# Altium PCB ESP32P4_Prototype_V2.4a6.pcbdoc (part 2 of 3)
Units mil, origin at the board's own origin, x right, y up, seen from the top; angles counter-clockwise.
Board outline 8474.8 x 7265.9 mil, 6 copper layers (Top Layer, GND, VCC, VCC1, GND1, Bottom Layer), stack 62.3 mil thick; 189 components, 155 nets, 775 pads, 406 vias.
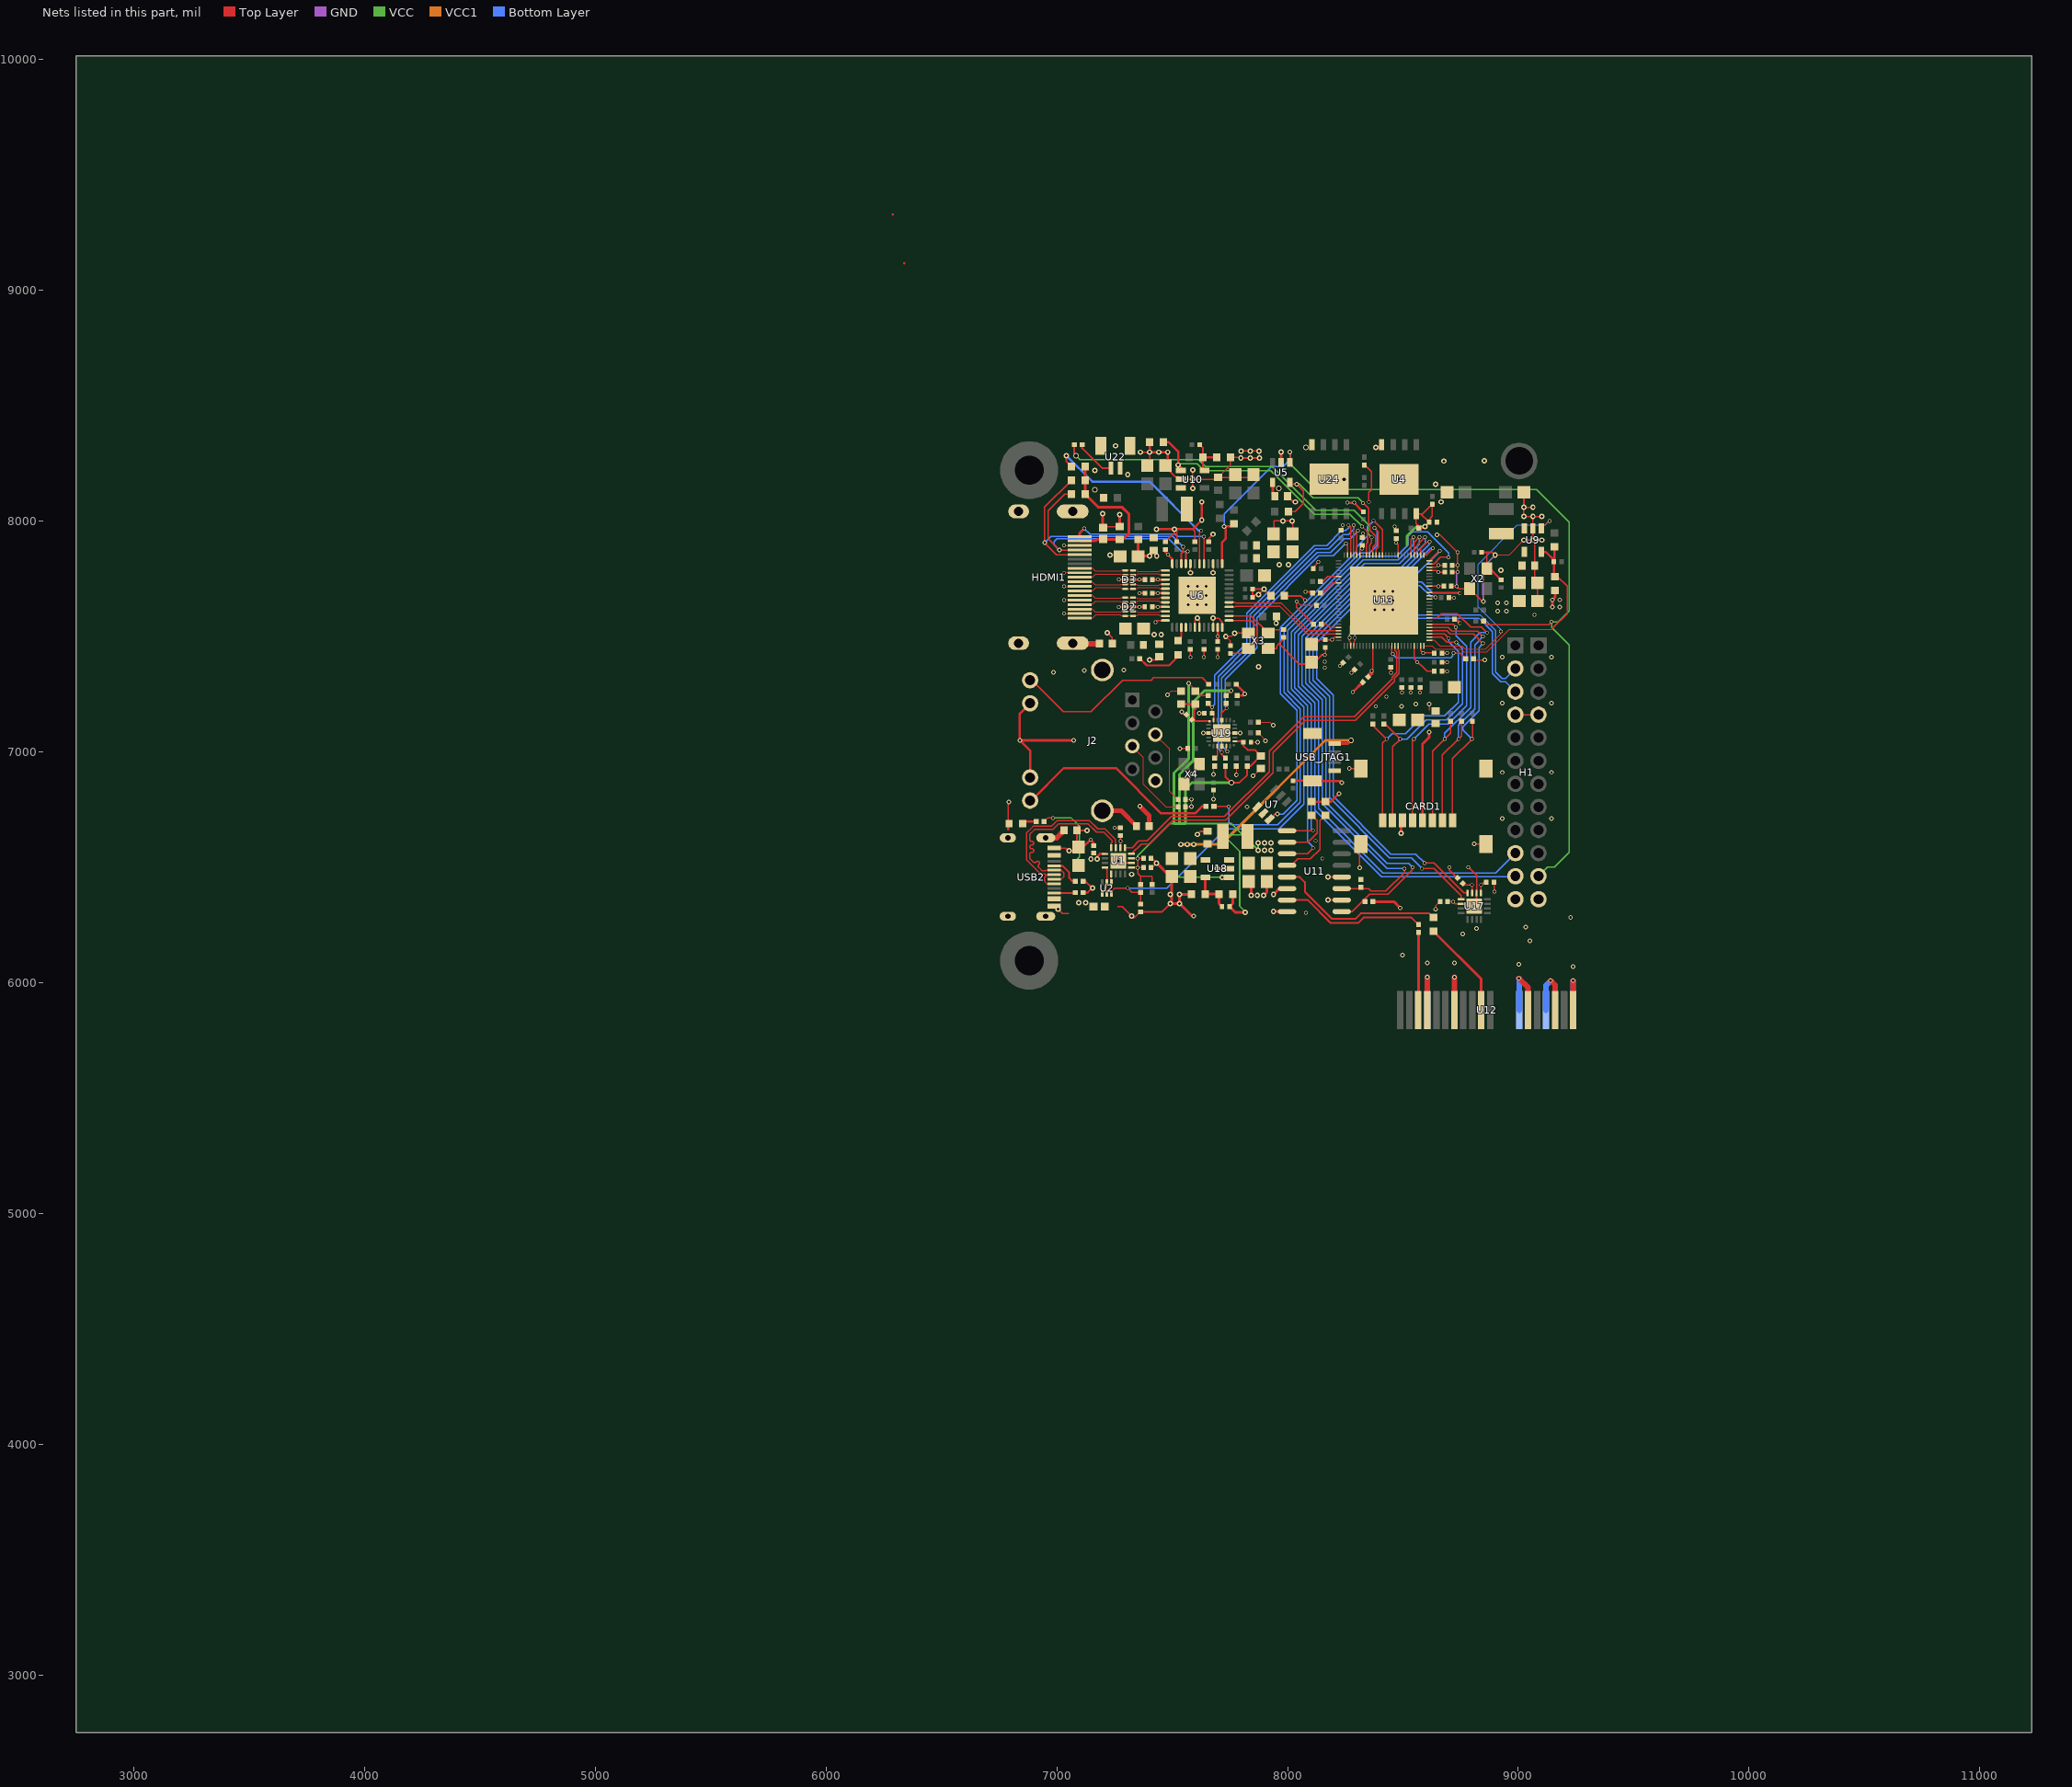
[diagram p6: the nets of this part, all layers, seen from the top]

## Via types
v1: diameter 15.7, hole 11.8, Top Layer to Bottom Layer, 168 vias
v2: diameter 23.6, hole 11.8, Top Layer to Bottom Layer, 139 vias
v3: diameter 19.7, hole 11.8, Top Layer to Bottom Layer, 91 vias
v4: diameter 23.6, hole 15.7, Top Layer to Bottom Layer, 8 vias

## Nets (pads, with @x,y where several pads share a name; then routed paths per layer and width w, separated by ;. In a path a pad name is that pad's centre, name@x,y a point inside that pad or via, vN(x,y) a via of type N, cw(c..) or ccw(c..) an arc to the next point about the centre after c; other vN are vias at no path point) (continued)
3V3_SYS: C2.1 C8.2 C9.2 C19.2 C27.2 C28.2 C29.2 C39.2 C40.2 C42.2 C43.2 C44.2 C45.2 C46.2 C47.2 C48.2 C49.2 C50.2 C51.2 C52.2 C53.2 C84.2 C85.2 C86.2 C90.2 C91.2 C92.2 C99.2 C101.2 C109.2 CARD1.4 L4.2 R1.1 R3.1 R6.2 R11.2 R15.1 R18.1 R19.2 R26.2 R41.2 R42.2 R43.2 U1.1 U1.3 U1.6 U3.2 U4.8 U5.4 U7.1 U9.4 U11.10 U11.12 U13.9 U13.21 U13.51 U13.62 U13.75 U13.77 U13.96 U13.101 U13.102 U17.1 U17.3 U17.6 U19.19 | length 6224.7
  Top Layer w4.7: v3@7573.5,7298.7 7573.5,7295.1 U3.2@7599.5,7269.2
  Top Layer w5: v1(7350.5,6538.2) v1(7350.5,6498.8) 7350.5,6472.2 7362.6,6460.1 7412.6,6460.1 ; v1(8587.6,7428.7) 8635.5,7428.7 C48.2@8636.1,7428.1
  Top Layer w5.9: U3.2@7600.8,7267.5 7624.1,7244.2 R41.2@7655.7,7244.2 ; R42.2@7734.4,7244.2 v3@7753.3,7263.1 ; C109.2@8116.3,7467.3 8134.8,7485.8 C53.2@8163.5,7485.8 8191.9,7485.8 v1(8193.1,7487) 8203.8,7497.7 U13.51@8220.9,7497.7 ; R18.1@8334.8,8243.6 8362.8,8215.6 8362.8,8135 8352.5,8124.7 v1(8352.5,8083.3) ; C52.2@8354.6,7325.7 8369.5,7340.6 U13.62@8369.5,7459.4 ; C46.2@8470.6,7925.2 v1(8470.6,7906.3) 8479.8,7897.1 U13.9@8479.8,7853.1 ; U13.75@8548.7,7459.4 8548.7,7404.5 8603.8,7349.4 C51.2@8636.1,7349.4 ; U13.77@8576.2,7459.4 8576.2,7440.1 v1(8587.6,7428.7) ; C84.2@8759.9,6430 8766.7,6423.2 v1(8799.3,6423.2) ; 8819.2,7398.4 v3(8854.5,7398.4) ; v1(8838.7,6423.2) 8851.3,6435.8 C86.2@8861.6,6435.8 ; 8576.9,8032.2 C2.1@8613.9,7995.3 ; 8576.9,8032.2 U4.8@8557.4,8032.2 8557.4,7990.6 8568.3,7979.7 R19.2@8568.3,7970.2 8588.9,7970.2 C2.1@8613.9,7995.3 ; 8576.9,8032.2 8585.7,8032.2 R15.1@8627.4,8073.9 8627.4,8021.7 8613.9,8008.2 C2.1@8613.9,7995.3
  Top Layer w6.1: U1.6@7275.7,6585.4 v1(7275.7,6612.9) ; v1@7275.7,6613 C39.2@7275.7,6637.8 ; U1.1@7323,6498.8 v1(7350.5,6498.8) C42.2@7375.3,6498.8 ; U1.3@7323,6538.2 v1(7350.5,6538.2) C40.2@7375.3,6538.2 ; R1.1@7362.6,6435.2 7362.6,6460 ; R3.1@7412.6,6435.2 7412.6,6460 ; U13.21@8314.4,7853.1 8314.4,7881.1 C45.2@8323,7889.7 ; C52.2@8349.3,7325.4 8349.3,7336.1 v1(8364.3,7351.1) ; U13.96@8614.6,7718.2 v1(8654,7718.2) C50.2@8676.8,7718.2 ; U13.101@8614.6,7787.1 8645.2,7787.1 v1(8653.1,7779.2) C49.2@8679.9,7779.2 ; U13.102@8614.6,7800.9 8645.2,7800.9 v1(8653.1,7808.8) C47.2@8679.9,7808.8 ; C85.2@8693.9,6351.1 v1(8717.5,6351.1) 8727.3,6341.3 U17.6@8752.1,6341.3 ; U17.3@8799.3,6388.5 v1(8799.3,6423.2) ; U17.1@8838.7,6388.5 v1(8838.7,6423.2)
  Top Layer w7.9: R11.2@7730.5,6938.4 7730.5,6892.5 v4(7756.1,6866.9) 7791.5,6866.9 7825,6900.4 R43.2@7825,6938.4 7839.3,6938.4 C99.2@7883.9,6983 7858.3,7008.6 7826.9,7008.6 7808.4,7027.1 C101.2@7808.4,7042.1 7804.5,7046 U19.19@7771.3,7046 ; v2(8175.8,6358) U11.10@8234.8,6358 ; v2(8175.8,6458) U11.12@8234.8,6458
  Top Layer w8: C52.2@8352.3,7330.8 8363.6,7342.1 8366,7342.1 ; C52.2@8354.3,7325.4 C52.2@8354.6,7325.7
  Top Layer w11.8: R6.2@7762.8,6383.7 7762.8,6343.3 C90.2@7749,6329.5 7773.7,6304.8 v2(7817.3,6304.8) ; U5.4@7935.2,8168.1 7935.2,8118.9 C19.2@7945,8109 ; CARD1.4@8584.8,6703.5 8584.8,7034.2 8614.3,7063.7 v3(8614.3,7085.4)
  VCC w6.1: 7812.9,6641.1 7805,6641.1 7745,6641.1 7736.9,6633 7736.9,6624.4 7792.6,6568.7 7792.6,6331.3 v2@7819.4,6304.4
  VCC w7.9: v1(7350.5,6538.2) 7350.5,6549.9 7490.3,6689.7 7508,6689.7 ; 7556.5,6689.7 7756.4,6689.7 7805,6641.1 v2(7872.5,6573.7) v2(7872.5,6605)
  VCC w11.8: v3(7571,7298) 7571,6971.2 7508,6908.2 7508,6689.7 7531.6,6689.7 ; v3(7755.7,7265) 7640.3,7265 7590.7,7215.3 7590.7,6961.4 7531.6,6902.3 7531.6,6689.7 ; v4(7756.1,6866.9) 7584.8,6866.9 7556.5,6838.6 7556.5,6689.7 7531.6,6689.7 ; 8517.9,7894.4 8517.9,7935.8 8559.2,7977.2 v2(8595.8,7977.2)
  other v1: 8562.6,7388.7 8323,7881.3
  other v2: 7900,6573.7 7927.6,6573.7 7900,6605 7927.6,6605 7964.7,7811.8 8004.1,7811.8
  other v3: 8911.1,7609.9 8949,7609.9 8911.1,7646.4 8949,7646.4
  other v4: 7962.7,8142.5
3V3AUX: R51.2 U12.B10 | length 428.3
  Top Layer w11.8: R51.2@8632,6223.1 8839.6,6015.5 U12.B10@8839.6,5880.8
5V_SYS: C4.1 C41.2 C87.2 C88.2 C89.2 D1.2 R5.1 U1.9 U18.1 U18.4 USB2.A4B9 USB2.B4A9 USB_JTAG1.1 | length 1594.7
  Top Layer w6.1: R5.1@6944.6,6698.7 6959.6,6713.7 v1(6982.6,6713.7)
  Top Layer w10: v2(7175.4,6536.2) 7175.4,6546 7187.1,6557.8 U1.9@7208.8,6557.8
  Top Layer w11.8: USB_JTAG1.1@8203.9,7036 8261.8,7036 v4(8275.7,7050)
  VCC w5.9: 7517.6,6468.7 7529.7,6456.6 v2(7717.2,6456.6)
  VCC w6.1: v1(6982.6,6713.7) 7062.6,6713.7 7097.6,6678.7 7097.6,6545 7075.1,6522.6
  VCC1 w11.8: v2(7537.5,6598.7) v2(7565,6598.7) v2(7592.6,6598.7) 7712.3,6598.7 8163.5,7050 v4(8275.7,7050)
  other v2: 7094.6,6347.2 7124.2,6347.2 7147.8,6536.2
12V_SYS: R53.2 U12.B3 | length 337.3
  Top Layer w11.8: U12.B3@8566.6,5880.8 8567.6,5881.8 R53.2@8567.6,6217.7
$1N39290: LED1.1 R5.2 | length 58.6
  Top Layer w10: LED1.1@6856.1,6688.7 6866.1,6698.7 R5.2@6910.6,6698.7
$1N39352: R4.2 USB2.B5 | length 106.8
  Top Layer w7.9: USB2.B5@6973.6,6388.5 7077.6,6388.5 R4.2@7079.6,6390.5
$1N39354: R2.2 USB2.A5 | length 147.5
  Top Layer w7.9: USB2.A5@6973.6,6506.6 7023.8,6506.6 7053.3,6477.1 7053.3,6453.5 7067.1,6439.7 R2.2@7079.6,6439.7
$1N39473: U20.2 USB2.1 USB2.2 USB2.3 USB2.4 | length 93.2
  Top Layer w23.6: USB2.1@6951.9,6627.7 6999.2,6627.7 U20.2@7031.6,6660.2
$1N39591: R51.1 U11.5 | length 750.9
  Top Layer w7.9: U11.5@7997.8,6458 8052.7,6458 8075,6435.8 8075,6394.4 8193.1,6276.3 8293.5,6276.3 8317.1,6300 8614.5,6300 R51.1@8632,6282.4
$1N39592: R53.1 U11.7 | length 633.7
  Top Layer w7.9: U11.7@7997.8,6358 8087.7,6358 8187.2,6258.6 8305.3,6258.6 8329,6282.4 8536.7,6282.4 R53.1@8567.6,6251.4
$1N39604: R50.2 U11.4 | length 328.2
  Top Layer w5.9: U11.4@7997.8,6508 8017.3,6508 8045.4,6536.2 8098.6,6536.2 8139.9,6577.5 8139.9,6701.4 R50.2@8163.5,6725
$1N39607: R49.2 U11.2 | length 233.4
  Top Layer w5.9: U11.2@7997.8,6608 8087.7,6608 8128.1,6648.4 8128.1,6701.4 R49.2@8104.5,6725
$4N12777: R27.1 U19.14 | length 57
  Top Layer w5.9: R27.1@7683.9,6972.5 7695,6983.7 U19.14@7695,7024.9
$4N12791: J2.SH1 J2.SH2 U8.2 | length 175.3
  Top Layer w19.7: J2.SH2@7197.2,6745 7278.7,6745 U8.2@7345,6678.7
$4N12794: J2.12 R9.2 | length 914.8
  Top Layer w10: J2.12@6884.2,6789.1 6889.3,6789.1 7030.1,6930 7255.7,6930 7451.9,6733.7 7598.9,6733.7 7628.9,6763.7 R9.2@7646.8,6763.7
$4N12797: J2.9 R8.2 | length 904.4
  Top Layer w5.9: J2.9@6884.2,7310.8 6891.8,7310.8 7028.9,7173.7 7147.5,7173.7 7284.6,7310.8 7408.6,7310.8 7419.4,7321.6 7630,7321.6 R8.2@7658.7,7292.9
$4N12802: C6.2 J2.4 | length 323.2
  Top Layer w4.7: J2.4@7425.3,7075.9 7488.9,7012.3 7488.9,6830.2 C6.2@7525,6794
$4N12803: C5.2 J2.5 | length 377.1
  Top Layer w4.7: J2.5@7325.3,7025.9 7373.9,6977.3 7373.9,6860.7 7472,6762.5 C5.2@7525,6762.5
$5N3531: MS_LED1.2 R34.1 | length 205.5
  Top Layer w7.9: R34.1@7360.4,7404.3 7389.9,7374.8 7485.8,7374.8 7525.9,7414.8 MS_LED1.2@7525.9,7426
$5N70958: HDMI1.20 HDMI1.21 HDMI1.22 HDMI1.23 U21.2 | length 117
  Top Layer w23.6: HDMI1.21@7069,7471.2 7071,7469.3 U21.2@7185.2,7469.3
$6N47: L2.1 U9.3
$6N67: L3.1 U10.3
$6N72: C36.1 R46.1 R47.2 U10.5 | length 181.4
  Top Layer w7.9: C36.1@7619.1,8331.5 7632.3,8318.3 R46.1@7632.3,8276.3 7632.3,8226.9 U10.5@7639.9,8219.3
  Top Layer w10: R46.1@7632.3,8276.3 R47.2@7692.9,8276.3
$6N85: L4.1 U18.3
$6N90: C90.1 R6.1 R7.2 U18.5 | length 193.4
  Top Layer w11.8: U18.5@7644,6456.6 7644,6385 R7.2@7642.8,6383.7 R6.1@7703.5,6383.7 7703.5,6341.9 C90.1@7715.9,6329.5
$10N53: R28.2 U13.32 | length 87.5
  Top Layer w5.9: R28.2@8142.1,7738.7 8152.6,7738.7 8173.4,7759.6 U13.32@8220.9,7759.6
$10N238: R48.2 U22.1 | length 175.5
  Top Layer w7.9: R48.2@7109.9,8331.5 7109.9,8316.2 7196,8230.1 U22.1@7234.4,8230.1
A1V2_MS: C3.2 C70.2 C73.2 C74.2 U6.27 U6.33 U16.2 | length 232.2
  Top Layer w10: C73.2@7414.1,7628.8 v1@7436.9,7628.8 ; C74.2@7414.3,7746.9 v1@7437.1,7746.9 ; v1(7437,7628.7) U6.33@7470.6,7628.7 ; v1@7437.2,7746.8 U6.27@7470.6,7746.8
  Top Layer w11.8: U16.2@7352.6,7921.1 7352.6,7851.3 7355.2,7848.7 v2@7401.3,7848.7
  other v1: 7437.2,7746.9
  other v2: 7402.6,7848.7 7432.8,7848.7
A3V3_DP83825I: C7.2 C100.2 U3.1 U19.6 | length 217.5
  Top Layer w7.9: C7.2@7538.5,7207.9 7538.8,7208.2 U3.1@7600.8,7208.2 7600.8,7186 7594.6,7179.9 7594.6,7148.1 ; C100.2@7585.5,7139 7594.6,7148.1 ; U19.6@7662.5,7133.6 7599.6,7133.6 7594.6,7138.5 7594.6,7148.1
A3V3_MS: C11.2 C69.2 C77.2 C78.2 C79.2 U6.24 U6.30 U6.47 U15.2 | length 192.7
  Top Layer w10: C78.2@7414.3,7687.8 v1@7437.1,7687.8 ; v1(7437.2,7687.8) U6.30@7470.6,7687.8 ; C77.2@7470.6,7877.9 7470.6,7865.7 v1(7481.9,7854.4) 7500.1,7836.2 U6.24@7500.1,7815.7 ; C79.2@7697,7478 v1(7697,7500.8) U6.47@7697,7540.1
  other v2: 7422.6,7508.7 7452.6,7508.7
CH343P0_USB_D+: U1.7 USB2.A6 USB2.B6 | length 849.6
  Top Layer w6.1: USB2.B6@6988.3,6428.1 6957.4,6428.1 6947.2,6438.3 6947.2,6457.2 6957.4,6467.5 ; U1.7@7256,6585.4 7256,6606.2 7253.3,6609 7253.3,6621 7208.1,6666.1 7177.3,6666.1 7141.9,6701.5 7000.1,6701.5 6976.4,6677.8 6897.3,6677.8 6868.2,6648.7 6868.2,6532.9 6930.9,6470.3 6950.9,6470.3 6953.7,6467.5 6957.4,6467.5 ; 6957.4,6467.5 USB2.A6@6988.3,6467.5 6957.4,6467.5
CH343P0_USB_D-: U1.8 USB2.A7 USB2.B7 | length 845.4
  Top Layer w6.1: 6898.8,6522.3 6882.3,6538.8 6882.3,6556.3 cw(c6890.3,6556.3) 6890.3,6564.3 6891.9,6564.3 ccw(c6891.9,6572.3) 6891.9,6580.3 6890.3,6580.3 cw(c6890.3,6588.3) 6890.3,6596.3 6891.9,6596.3 ccw(c6891.9,6604.3) 6891.9,6612.3 6890.3,6612.3 cw(c6890.3,6620.3) 6882.3,6620.3 6882.3,6642.9 6903.2,6663.7 6982.3,6663.7 7006,6687.4 7136,6687.4 7171.5,6652 7202.3,6652 7239.2,6615.1 7239.2,6609 7236.4,6606.2 U1.8@7236.4,6585.4 ; 6898.84,6522.34 ccw(c6904.5,6528) 6910.16,6522.34 ; 6910.1,6522.3 6911.7,6523.9 ; 6911.74,6523.86 cw(c6917.4,6518.2) 6923.06,6512.54 ; 6921.4,6499.7 6936.7,6484.4 6950.9,6484.4 6953.7,6487.2 USB2.B7@6988.3,6487.2 7019.2,6487.2 7029.5,6476.9 7029.5,6458 7019.2,6447.8 USB2.A7@6988.3,6447.8 ; 6921.4,6511 6923,6512.6 ; 6921.44,6499.64 cw(c6927.1,6505.3) 6921.44,6510.96
CH343P0_USB_DTR: U1.12 U2.1 U2.5 | length 125.2
  Top Layer w6.1: U2.1@7197,6385 7197,6398.1 7216.7,6417.8 U2.5@7216.7,6435.4 7216.7,6490.9 U1.12@7208.8,6498.8
CH343P0_USB_RTS: U1.13 U2.2 U2.4 | length 94.4
  Top Layer w6.1: U2.2@7216.7,6384.4 7216.7,6397.5 7236.4,6417.2 U2.4@7236.4,6434.8 ; U2.4@7236.4,6435.4 U1.13@7236.4,6471.2
CH343P0_USB_RXD: U1.5 U13.69 | length 1666.5
  Top Layer w5: U1.5@7295.4,6585.4 7326.9,6585.4 7355.2,6613.7 7390.7,6613.7 7496.2,6719.3 7726.5,6719.3 7921.4,6914.1 7921.4,7002.7 8071.1,7152.4 8289.6,7152.4 8452.9,7315.7 8452.9,7323.7 8472.6,7343.4 8472.6,7433.7 8466,7440.3 U13.69@8466,7459.4
CH343P0_USB_TXD: U1.4 U13.70 | length 1663.2
  Top Layer w5: U1.4@7323,6557.9 7366.3,6601.1 7401.7,6601.1 7504.3,6703.7 7731.2,6703.7 7936.4,6908.9 7936.4,6996.5 8077.3,7137.4 8293.8,7137.4 8462.6,7306.3 8462.6,7319.7 8482.3,7339.4 8482.3,7439 8479.8,7441.5 U13.70@8479.8,7459.4
CHIP_PU: C1.2 R1.2 U2.3 U13.103 | length 2945.3
  Top Layer w5: U13.103@8614.6,7814.7 8633.6,7814.7 8662.6,7843.7 v1(8697.6,7843.7)
  Top Layer w6.1: U2.3@7236.4,6385 7236.4,6394.4 7251.7,6409.8 v1(7307.3,6409.8) 7325.5,6391.7 R1.2@7362.6,6391.7 C1.2@7362.6,6340.2
  Bottom Layer w5.9: v1(7307.3,6409.8) 7476.1,6409.8 7732.4,6666.1 7962.7,6666.1 8071.2,6774.5 8071.2,7193.8 8000.1,7264.9 8000.1,7526.7 8320.6,7847.2 8472.8,7847.2 8523.8,7898.2 8523.8,7935.8 8541.5,7953.5 8606.4,7953.5 8697.6,7862.4 v1(8697.6,7843.7)
CSI_REXT: R30.2 U13.48 | length 79.8
  Top Layer w6.1: R30.2@8147.1,7553.7 8169.5,7553.7 8184.1,7539.1 U13.48@8220.9,7539.1
DM_HID: H1.22 U13.55 | length 1064.4
  Top Layer w6.1: v1(8268.1,7494.7) 8268.1,7480.8 8272.9,7476 8272.9,7459.5 U13.55@8273.1,7459.4
  Bottom Layer w6.1: v1(8268.1,7494.7) 8268.1,7508.7 8272.9,7513.5 8272.9,7547.7 8319.2,7594 8834.8,7594 8902,7526.8 8902,7345.6 8929.2,7318.4 8944.6,7318.4 H1.22@8987.6,7361.4
DM_MS: U6.5 U13.49 | length 525.5
  Top Layer w6.1: U6.5@7746.2,7648.4 7772,7648.4 7774.8,7645.6 7971.5,7645.6 8091.8,7525.4 U13.49@8220.8,7525.4
DP_HID: H1.20 U13.56 | length 1068.9
  Top Layer w6.1: U13.56@8286.8,7459.4 8287,7459.5 8287,7476 8291.8,7480.8 v1(8291.8,7494.7)
  Bottom Layer w6.1: v1(8291.8,7494.7) 8291.8,7508.7 8287,7513.5 8287,7541.8 8293.8,7548.6 ; 8293.74,7548.56 cw(c8299.4,7542.9) 8305.06,7548.56 ; 8305.1,7548.6 8308.5,7545.1 ; 8308.54,7545.14 ccw(c8314.2,7550.8) 8319.86,7556.46 ; 8316.34,7559.84 cw(c8322,7565.5) 8316.34,7571.16 ; 8316.4,7559.9 8319.8,7556.5 ; 8316.4,7571.2 8325.1,7579.9 8828.9,7579.9 8887.9,7521 8887.9,7339.8 8923.3,7304.3 8944.6,7304.3 H1.20@8987.6,7261.4
DP_MS: U6.4 U13.50 | length 525.5
  Top Layer w6.1: U6.4@7746.2,7628.7 7772,7628.7 7774.8,7631.5 7965.7,7631.5 8085.7,7511.4 U13.50@8220.8,7511.4
DSI_REXT: R29.2 U13.34 | length 96.7
  Top Layer w5.9: R29.2@8142.1,7688.7 8152.6,7688.7 8195.9,7732 U13.34@8220.9,7732
EMMC_CLK: CARD1.5 U13.84 | length 1122.6
  Top Layer w5.9: CARD1.5@8541.5,6703.5 8541.5,7050 v1(8547.4,7055.9) ; U13.84@8614.6,7552.9 8717.7,7552.9 v1@8730.5,7540.1
  Bottom Layer w5.9: v1(8547.4,7055.9) 8612.4,7120.8 8696,7120.8 8775.8,7200.7 8775.8,7458.3 8730.5,7503.6 v1@8730.5,7540.1
  other v1: 8728.6,7540.9
EMMC_CMD: CARD1.3 R14.2 U13.86 | length 1308.3
  Top Layer w5.9: U13.86@8614.6,7580.4 8647.9,7580.4 8666.7,7599.2 8735.2,7599.2 8793.5,7540.9 8840.7,7540.9 v1(8864.3,7517.3) ; CARD1.3@8628.1,6703.5 8628.1,7002.7 v1(8681.3,7055.9) 8706.8,7081.5 R14.2@8706.8,7133.3
  Bottom Layer w5.9: v1(8681.3,7055.9) 8681.3,7081.1 8793.5,7193.3 8793.5,7476 8834.8,7517.3 v1(8864.3,7517.3)
EMMC_D0: CARD1.7 R16.2 U13.80 | length 1200.8
  Top Layer w5.9: R16.2@8417.5,7121.5 8422.7,7121.5 v1(8488.3,7055.9) 8454.9,7022.4 CARD1.7@8454.9,6703.5 ; U13.80@8614.6,7497.7 8668.5,7497.7 8691.1,7475.2 v1(8730.5,7475.2)
  Bottom Layer w5.9: v1(8488.3,7055.9) 8517.9,7055.9 8600.5,7138.5 8688.7,7138.5 8758.1,7208 8758.1,7447.5 v1(8730.5,7475.2)
EMMC_D1: CARD1.8 R17.2 U13.81 | length 1216
  Top Layer w4: v1(8698.4,7492.9) v1@8700.9,7492.9
  Top Layer w5.9: R17.2@8370.2,7121.5 8370.2,7114.9 v1(8429.3,7055.9) 8411.6,7038.2 CARD1.8@8411.6,6703.5 ; U13.81@8614.6,7511.5 8679.8,7511.5 v1(8698.4,7492.9)
  Bottom Layer w5.9: v1(8429.3,7055.9) 8452.9,7079.5 8512,7079.5 8588.7,7156.3 8681.3,7156.3 8740.4,7215.3 8740.4,7434.7 8698.4,7476.7 v1(8698.4,7492.9)
EMMC_D2: CARD1.1 R12.2 U13.82 | length 1187.2
  Top Layer w5.9: U13.82@8614.6,7525.3 8691,7525.3 8704.9,7511.4 8805.3,7511.4 v1(8846.6,7470.1) ; CARD1.1@8714.7,6703.5 8714.7,6971.2 v1(8799.4,7055.9) 8801.3,7057.8 R12.2@8801.3,7133.3
  Bottom Layer w5.9: v1(8799.4,7055.9) 8759.6,7095.7 8759.6,7109.3 8828.9,7178.7 8828.9,7452.4 v1(8846.6,7470.1)
EMMC_D3: CARD1.2 R13.2 U13.83 | length 1200.2
  Top Layer w5.9: U13.83@8614.6,7539.1 8696.1,7539.1 8711.9,7523.2 8823,7523.2 v1(8846.6,7499.6) ; CARD1.2@8671.4,6703.5 8671.4,6987 v1(8740.3,7055.9) 8754.1,7069.6 R13.2@8754.1,7133.3
  Bottom Layer w5.9: v1(8740.3,7055.9) 8740.3,7115.1 8811.2,7186 8811.2,7464.2 v1(8846.6,7499.6)
EMMC_D4: U13.87
EMMC_D5: U13.88
ESP32P4_EN_DCDC: U9.1 U13.79 | length 1129.7
  Top Layer w4.7: U13.79@8614.6,7484 8637.3,7484 8663,7458.3 8757.4,7458.3 8769.2,7446.5 8858.4,7446.5 8923.3,7511.4 v1@8923.3,7523.2 ; U9.1@9100.6,7969.1 9132.6,8001.1 v1(9135.7,8001.1)
  Bottom Layer w4.7: v1@8923.3,7523.2 8923.3,7530.4 8825,7628.7 8825,7811.8 8996.2,7983 9117.6,7983 v1(9135.7,8001.1)
  other v1: 8925.3,7522.4
ESP32P4_FB_DCDC: C30.1 R44.1 R45.2 U9.5 U13.78 | length 1089.3
  Top Layer w4.7: U13.78@8590,7459.4 8626.9,7459.4 8640.6,7445.7 8752.2,7445.7 8764,7433.9 8863.5,7433.9 8959.9,7530.3 9142.8,7530.3 9147.5,7535
  Top Layer w5: 9147.5,7535 9212.4,7599.9 9212.4,7717.9 9170.9,7759.4 R45.2@9159.3,7759.4
  Top Layer w10: U9.5@9100.6,7866.8 9119,7866.8 9157,7828.7 R44.1@9157,7889.4 ; C30.1@9155.3,7824.1 9155.3,7763.3 R45.2@9159.3,7759.4
ETH_INT_PWDN: R42.1 U13.25 U19.3 | length 1104.5
  Top Layer w5.9: U19.3@7714.8,7138.1 7714.8,7169.1 v1(7735.7,7190) 7735.7,7208.8 R42.1@7734.4,7210.1
  Top Layer w6.1: v1(8252.6,7903.7) 8259.3,7897 U13.25@8259.3,7853.1
  Bottom Layer w5.9: v1(7735.7,7190) 7729.7,7195.9 7729.7,7314.3 7867.6,7452.2 7867.6,7582.1 8134.9,7849.4 8198.3,7849.4 v1(8252.6,7903.7)
ETH_LED_GPIO15: R9.1 U13.16 | length 2042
  Top Layer w5.9: R9.1@7680.9,6763.7 v1(7744.8,6763.7) 7753.3,6763.7 ; v1(8376.1,7971.2) 8393.9,7953.5 8393.9,7888.5 8383.3,7878 U13.16@8383.3,7853.1
  Bottom Layer w5.9: v1(7744.8,6763.7) 7744.8,6695.1 7756.1,6683.8 7956.8,6683.8 8055.4,6782.4 8055.4,7187.3 7984.4,7258.4 7984.4,7533.2 8314.1,7863 8356.4,7863 8387.9,7894.4 8387.9,7959.4 v1(8376.1,7971.2)
ETH_RST_N: C98.2 R41.1 U13.24 U19.5 | length 1289.2
  Top Layer w5: v1@8264.9,7982.8 8273.1,7974.6 U13.24@8273.1,7853.1
  Top Layer w5.9: R41.1@7655.7,7210.1 v1(7672.3,7193.4) C98.2@7672.3,7167.9 ; C98.2@7677.3,7167.9 7679.3,7165.9 U19.5@7679.3,7138
  Bottom Layer w5.9: v1(7672.3,7193.4) 7684.7,7205.8 7684.7,7333 7822.6,7470.8 7822.6,7600.7 8116.3,7894.4 8169.4,7894.4 8234.4,7959.4 8252.1,7959.4 8264.9,7972.2 v1@8264.9,7982.8
  other v1: 8263.9,7983
GND: C1.1 C2.2 C3.1 C4.2 C5.1 C6.1 C7.1 C8.1 C9.1 C10.1 C11.1 C12.1 C13.1 C14.2 C15.2 C16.1 C17.2 C18.2 C19.1 C20.1 C27.1 C28.1 C29.1 C31.1 C32.1 C33.1 C34.1 C35.1 C37.1 C38.1 C39.1 C40.1 C41.1 C42.1 C43.1 C44.1 C45.1 C46.1 C47.1 C48.1 C49.1 C50.1 C51.1 C52.1 C53.1 C55.1 C56.1 C57.1 C58.1 C59.1 C60.1 C61.1 C62.1 C63.1 C64.1 C65.1 C66.1 C67.1 C68.1 C69.1 C70.1 C71.1 C72.1 C73.1 C74.1 C75.1 C76.1 C77.1 C78.1 C79.1 C80.1 C81.1 C82.1 C84.1 C85.1 C86.1 C87.1 C88.1 C89.1 C91.1 C92.1 C96.2 C97.1 C98.1 C99.1 C100.1 C101.1 C109.1 CARD1.6 CARD1.9 CARD1.10 CARD1.11 CARD1.12 D1.1 D2.3 D2.8 D3.3 D3.8 D4.1 H1.1 H1.2 H1.17 H1.18 HDMI1.2 HDMI1.5 HDMI1.8 HDMI1.11 HDMI1.17 J2.8 J2.10 J2.11 LED1.2 R2.1 R4.1 R7.1 R10.2 R21.1 R22.1 R23.1 R27.2 R29.1 R30.1 R32.1 R45.1 R47.1 R49.1 R50.1 R52.1 R54.1 R59.2 R60.2 R62.2 R63.2 U1.2 U1.17 U4.4 U4.9 U5.2 U6.15 U6.20 U6.36 U6.42 U6.43 U6.46 U6.48 U6.49 U7.2 U8.1 U9.2 U10.2 U11.6 U11.8 U12.A4 U12.A12 U12.A15 U12.A18 U12.B4 U12.B7 U12.B13 U12.B16 U12.B18 U13.105 U17.2 U17.17 U18.2 U19.9 U19.21 U19.25 U20.1 U21.1 U22.2 U22.3 U22.4 U24.4 U24.9 USB2.A1B12 USB2.B1A12 USB_JTAG1.4 USB_JTAG1.5 USB_JTAG1.6 X2.2 X2.4 X3.2 X3.4 X4.2 X4.4 | length 12562.8
  Top Layer w4: v3@7476.5,7244.8 7494.7,7263.1 C7.1@7538.5,7263.1
  Top Layer w4.1: v2(8899.7,7852.8) 8958.7,7852.8 v2(9023.8,7917.9)
  Top Layer w4.7: C5.1@7558.1,6762.5 v3(7583.8,6762.5) v3(7583.8,6794) C6.1@7558.1,6794 ; v3(7616.5,7168.2) 7638.9,7168.2 C98.1@7639.2,7167.9 ; v3(7635.6,7081.5) U19.9@7658.1,7081.5 ; v3@7677.9,6900.7 7677.9,6932.5 R27.2@7683.9,6938.4 ; v3@7678.9,6793.3 C96.2@7678.9,6834.1 ; U19.21@7771.3,7081.5 v3(7793.9,7081.5) ; v3(7777.7,6900.7) R59.2@7777.7,6938.4 ; C101.1@7841.5,7042.1 v3(7869.8,7042.1) ; v3@7848.4,6897 7852.9,6897 C99.1@7883.9,6927.9 ; R63.2@7872.8,7082.9 7903.9,7051.8 v3(7903.9,7048.7) ; R60.2@7873.7,7128.7 7923.4,7128.7 v3(7937.2,7114.9)
  Top Layer w4.9: v1(7031.7,7599.2) HDMI1.2@7106.7,7599.2 ; v1(7031.7,7658.2) HDMI1.5@7106.7,7658.2 ; v1(7031.7,7717.3) HDMI1.8@7106.7,7717.3 ; v1(7031.7,7776.4) HDMI1.11@7106.7,7776.4 ; v1(7031.7,7894.5) HDMI1.17@7106.7,7894.5
  Top Layer w5: USB2.B1A12@6973.6,6331.5 6996.2,6331.5 v2@7008,6319.6 ; USB2.A1B12@6973.6,6583.4 7039,6583.4 v2@7053.3,6569.2 ; v2@7229,7854.6 7294.1,7854.6 C70.1@7300,7848.7 ; v2(7362.6,8298.7) v2(7402,8298.7) 7402,8251 C38.1@7391.9,8240.9 ; C42.1@7408.4,6498.8 7412.7,6498.8 v2(7432.6,6518.7) 7413.1,6538.2 C40.1@7408.4,6538.2 ; C11.1@7444.4,7407.4 C11.1@7445,7408.5 ; C77.1@7470.6,7911 7510,7950.4 v2(7510,7965.3) 7519.8,7955.5 C82.1@7519.8,7911 ; C37.1@7470.6,8240.9 7470.6,8235.7 7512.6,8193.7 7525.7,8193.7 U10.2@7537.5,8181.9 v2(7588.7,8181.9) ; v2(7578.9,7776.4) U6.20@7578.9,7815.7 ; 7588.7,7965.3 7598.6,7955.5 C76.1@7598.6,7911 ; v2(7588.7,8142.5) v2(7588.7,8181.9) ; v2(7588.7,8221.2) v2(7588.7,8181.9) ; U6.42@7598.6,7540.1 7598.6,7569.7 v2(7608.4,7579.5) 7618.3,7569.7 U6.43@7618.3,7540.1 ; C81.1@7657.6,7911 7657.6,7923.7 v2(7677.6,7943.7) ; U6.46@7677.3,7540.1 v2(7677.3,7579.5) 7700.9,7579.5 7716.7,7563.7 U6.48@7716.7,7540.1 ; v2(7677.3,7776.4) U6.15@7677.3,7815.7 ; C35.1@7699,8189.7 7691.1,8181.9 v2(7588.7,8181.9) ; v1(8732.7,7718.1) 8743.2,7707.6 X2.2@8789,7707.6 ; X2.4@8863.8,7794.3 8863.8,7864.9 ; v2(9063.2,7917.9) 9071.1,7910.1 C29.1@9071.1,7807.7 9071.1,7744.7 C28.1@9082.9,7732.9 C27.1@9082.9,7654.2
  Top Layer w5.4: v1(7428.2,7561.7) 7434.9,7568.4 U6.36@7470.4,7568.4
  Top Layer w5.9: v2(7006.1,6317.7) 7023.8,6300 7052.5,6300 ; D4.1@7200.9,7972.1 7205.1,7976.3 C20.1@7272.6,7976.3 ; v2(7218.7,7516.5) 7240.3,7494.8 U21.1@7240.3,7469.3 ; 7263.9,6329.5 7282.6,6329.5 v2(7323.4,6288.7) ; v3(7533.9,7014.5) C97.1@7568.2,7014.5 ; v3@7539,7173.7 7550.3,7162.4 C100.1@7562.2,7162.4 ; X4.2@7551.3,6861 7551.3,6870.8 v3(7584.8,6904.3) 7618.3,6937.8 X4.4@7618.3,6947.6 ; U19.9@7658.1,7081.5 U19.25@7714.7,7081.5 U19.21@7771.3,7081.5 ; C44.1@7939.1,7945.6 7941.1,7947.6 7941.1,8000.7 v2(7980.5,8000.7) v2(8019.8,8000.7) 8021.8,7998.8 C43.1@8021.8,7945.6 ; C19.1@8000.2,8109 8025.7,8083.4 v2(8033.6,8083.4) ; v1(8039.5,7652.3) 8039.5,7627.2 R30.1@8113,7553.7 ; C60.1@8111.6,7794.1 8111.6,7801.1 v1(8134,7823.6) ; v1@8163.5,7422.9 C53.1@8163.5,7452.7 ; v3(8267.9,6927.9) CARD1.9@8312.2,6927.9 ; v3(8312.2,6497.8) CARD1.10@8312.2,6601.1 ; v1@8447.6,7343.9 C63.1@8447.6,7367.2 ; v1(8464.7,7977.1) 8464.7,7964.1 C46.1@8470.6,7958.2 ; 8614.3,7179.9 v3(8614.3,7207) ; v1(8700.9,6500.7) 8700.9,6488.9 C84.1@8736.5,6453.4 ; v1(8783.6,6500.7) 8819,6465.4 U17.2@8819,6388.5 ; v3(8809.2,6601.1) CARD1.11@8853.5,6601.1 ; C86.1@8894.6,6435.8 8895.8,6434.6 v1(8895.8,6394.4)
  Top Layer w6.1: v1(7250.9,6670.8) C39.1@7275.7,6670.8 ; v2(7265.9,6528.3) 7275.7,6518.5 U1.2@7323,6518.5 ; v2@7327.8,6282.2 7337.6,6282.2 C1.1@7362.6,6307.2 ; v1(7578.7,7410.2) 7578.8,7410.3 C75.1@7578.8,7444.9 ; v1(7637.8,7410.2) 7637.9,7410.3 C80.1@7637.9,7444.9 ; v1(7696.9,7410.2) 7697,7410.3 C79.1@7697,7444.9 ; C17.2@7752.6,7460.2 7752.6,7480.1 v2(7731.9,7500.8) 7756.4,7500.8 v2(7770.8,7515.1) X3.4@7829.9,7515.1 ; v2(7798.2,8303.7) v2(7837.6,8303.7) v2(7877,8303.7) 7877.6,8303.1 v2(7877.6,8273.7) v2(7837.6,8273.7) v2(7797.6,8273.7) 7795,8276.3 R47.1@7752.3,8276.3 7752.3,8243 C35.1@7699,8189.7 7840.7,8189.7 C33.1@7852.5,8201.5 ; X3.2@7916.5,7448.2 7953.5,7448.2 7953.5,7460 7962.7,7469.3 7982.6,7489.1 C18.2@7982.6,7497.2 ; v1(8039.5,7652.3) 8057.2,7634.6 8124.6,7634.6 C65.1@8125.6,7635.6 ; v1(8077.6,7693.7) 8103.6,7693.7 R29.1@8108.5,7688.7 ; C57.1@8232.6,7960.2 8238.5,7966.1 v1(8238.5,7983.1) ; C45.1@8323,7928.7 8326.9,7932.6 v1(8326.9,7947.6) ; v1(8495.5,7256.7) C59.1@8495.5,7279.5 ; v1(8534.8,7256.7) C61.1@8534.8,7279.5 ; v1(8574.2,7256.7) C64.1@8574.2,7279.5 ; v3(8641.9,6317.7) 8641.9,6332.3 C85.1@8660.8,6351.2 ; v3(8647.8,7941.7) 8659.6,7941.7 v1(8736.6,7864.7) v1(8736.6,7808.7) ; C51.1@8669.1,7349.3 v1(8691.9,7349.3) ; C55.1@8669.1,7388.7 v1(8691.9,7388.7) ; C48.1@8669.1,7428 v1(8691.9,7428) ; C56.1@8699.1,7668.6 v1(8721.9,7668.6) ; C50.1@8709.9,7718.1 v1(8732.7,7718.1) ; C49.1@8713.8,7779.1 v1(8736.6,7779.1) v1(8736.6,7808.7) ; C47.1@8713.8,7808.7 v1(8736.6,7808.7) ; X2.2@8789,7707.6 8843.9,7652.8 v3@8849.8,7652.8 ; H1.18@8987.6,7161.4 H1.17@9087.6,7161.4 ; U9.2@9063.2,7984.3 v2(9063.2,8020.3) ; v2(9063.2,8059.7) v2(9023.8,8059.7) v2(9023.8,8020.3) v2(9063.2,8020.3) ; v2(9102.6,8020.3) v2(9063.2,8020.3)
  Top Layer w7.9: LED1.2@6789.1,6688.7 6789.1,6780.2 v3(6792.6,6783.7) ; C4.2@7093.5,6588.5 7086.8,6595.2 U20.1@7086.8,6660.2 v2(7130.1,6660.2) ; R4.1@7113.6,6390.5 7134.5,6390.5 v2(7154.2,6410.2) 7124.7,6439.7 R2.1@7113.6,6439.7 ; C1.1@7362.6,6307.2 7456.2,6307.2 v2(7492.3,6343.3) ; v2(7401.7,7398.4) 7434.8,7398.4 C11.1@7445,7408.5 ; v2(7608.4,6642.5) 7622.2,6656.3 C89.1@7653.1,6656.3 ; v2@7898.2,7705.5 v2(7897.8,7705.5) ; R22.1@7927.2,7675.9 7897.8,7705.3 v2(7897.8,7705.5) ; 7962.7,7469.3 8051.3,7380.7 8116.3,7380.7 8116.3,7388.5 8147.8,7420.1 v1(8160.8,7420.1) ; v1(8809.2,6331.5) 8819,6341.3 U17.2@8819,6388.5 ; C16.1@8841.5,7864.9 8863.8,7864.9 8887.6,7864.9 v2(8899.7,7852.8) ; X2.4@8863.8,7794.3 8876.7,7794.3 C15.2@8925.3,7745.6 ; v2(9023.8,8059.7) C31.1@9023.8,8124.7 ; v2(7897.8,7705.5) v2(7874.2,7681.9) 7860.9,7681.9 C71.1@7849.1,7670 7848.6,7670.5 C72.1@7848.6,7705.5 v2(7897.8,7705.5)
  Top Layer w9.8: R49.1@8104.5,6784.3 R50.1@8163.5,6784.3 8187.3,6784.3 v3(8222.6,6819.6)
  Top Layer w10: 6789.1,6664.5 LED1.2@6789.1,6688.7 ; J2.11@6884.2,6889.1 6884.2,7005.5 v3(6839.7,7050) ; J2.10@6884.2,7210.8 6839.7,7166.3 v3(6839.7,7050) ; v2(7053.3,6571.6) 7078.9,6571.6 C4.2@7094.6,6587.4 ; v3(7072.4,7050) v3(6839.7,7050) ; C4.2@7093.5,6588.5 C4.2@7094.6,6587.4 ; C41.1@7159.6,6594.1 7159.6,6606.3 v1(7146.1,6619.9) 7113.5,6587.4 C4.2@7094.6,6587.4 ; v1(7268.1,7628.7) D2.8@7296.9,7628.7 D2.3@7329.5,7628.7 v1(7358.2,7628.7) ; v1(7268.1,7746.9) 7296.9,7746.9 7329.5,7746.9 v1(7358.4,7746.9) ; v1@7358.3,7628.7 C73.1@7381.1,7628.7 ; v1@7358.5,7687.8 C78.1@7381.2,7687.8 ; v1@7358.5,7746.8 C74.1@7381.2,7746.8 ; R21.1@7401.6,8343.3 7402,8342.9 v2(7402,8298.7) v2(7441.3,8298.7) v2(7480.7,8298.7) 7480.7,8251 C37.1@7470.6,8240.9 ; v2(7431.3,7965.3) v2(7510,7965.3) 7588.7,7965.3 v2(7628.1,8004.7) v2(7628.1,8083.4) ; R62.2@7777.8,7292.9 7777.8,7291 7815.7,7253.1 7806.7,7244.2 R10.2@7781.6,7244.2 ; C13.1@8023.7,6874.9 8107.1,6874.9 USB_JTAG1.5@8107.4,6874.6 8226.7,6874.6 v3(8234.4,6866.9) ; v1(8258.6,8079.5) v1(8288.4,8079.5) 8323,8044.9 C14.2@8323,8040.9 ; v2(9063.2,7917.9) U9.2@9063.2,7969.1 U9.2@9063.2,7984.3
  Top Layer w11.8: D4.1@7198.9,7980.2 7199,7980.3 v2(7199,8032) ; C20.1@7272.6,7976.3 7272.7,7976.4 v2(7272.7,8028.1) ; v2(7432.6,6518.7) 7491.9,6459.4 C87.1@7498.1,6459.4 7498.1,6349.1 v2(7492.3,6343.3) v2(7531.6,6343.3) ; R7.1@7583.5,6383.7 7582.4,6382.6 v2(7531.6,6382.6) v2(7531.6,6343.3) ; v3(7592.6,6288.7) 7586.2,6288.7 v2(7531.6,6343.3) ; v2(7695.2,6494) U18.2@7746.4,6494 ; C91.1@7831.5,6438.8 7841.6,6428.7 v2(7841.6,6378.2) ; v2(7896.7,6378.2) 7910.2,6391.7 C92.1@7910.2,6438.8 ; v2(7939.1,6308) U11.8@7997.8,6308 ; v2(7939.1,6382.6) 7964.5,6408 U11.6@7997.8,6408 ; U5.2@7972.6,8260.6 v2(7972.6,8299.9) ; v1(8160.8,7420.1) v1@8163.5,7422.9 ; v1@8229.2,7375.9 8229.6,7375.9 C58.1@8240.4,7386.7 ; v1@8279.7,7346.2 8280.1,7346.2 C62.1@8292.2,7358.3 ; v1@8284.7,7261.2 8285.1,7261.2 C52.1@8325.9,7302 ; R54.1@8369.6,6351.1 8460.8,6351.1 v3(8488.3,6323.6) ; v2@8383.9,8319.6 8395.6,8319.6 U4.4@8407.4,8331.5 ; v2(8492.3,6647.6) CARD1.6@8492.3,6703.5 ; C67.1@8723.9,7574.8 8730.1,7574.8 v1(8746.3,7558.6) ; v3(9147.5,7627.3) v3(9147.5,7658.9) 9159.3,7670.7 R45.1@9159.3,7700
  Top Layer w20: v3(7359.4,6765) 7400.1,6724.2 U8.1@7400.1,6678.7
  Top Layer w23.6: U12.B4@8605.6,5880.8 v3(8605.6,6023.7) ; U12.B7@8722.6,5880.8 v3(8722.6,6023.7) ; v3(9002.6,6018.7) 9042.6,5978.7 U12.B13@9042.6,5880.8 ; v3(9140.5,6008.7) 9159.6,5989.6 U12.B16@9159.6,5880.8 ; U12.B18@9237.6,5880.8 v3(9237.6,6008.7)
  GND w6.1: v1(8732.7,7718.1) 8732.7,7775.2 v1(8736.6,7779.1) ; v3(8848.6,7652.3) 8848.6,7801.7 v2(8899.7,7852.8) ; v2(9023.8,7917.9) v2(9063.2,7917.9) v2(9102.6,7917.9)
  Bottom Layer w23.6: U12.A4@8605.6,5880.8 v3(8605.6,6023.7) ; v3(9002.6,6018.7) 9003.6,6017.7 U12.A12@9003.6,5880.8 ; U12.A15@9120.6,5880.8 9120.6,5988.8 v3(9140.5,6008.7) ; U12.A18@9237.6,5880.8 v3(9237.6,6008.7)
  other v1: 8079.6,6301.9 8150.4,6537.9 8120.9,6614.6 8382,7197.6 8427.7,7240 8282.6,7258.7 8277.6,7343.7 8447.6,7343.7 8160.8,7364.4 8227.1,7373.4 8160.8,7391.4 9070.8,7594 7358.4,7687.8
  other v2: 7869.2,6378.2 7492.3,6382.6 7324.9,6469.2 7874.2,7368.9 7950.9,7557.8 8378.4,7616.8 8417.7,7616.8 8457.1,7616.8 7569,7638.6 7608.4,7638.6 7647.8,7638.6 8378.4,7656.2 8417.7,7656.2 8457.1,7656.2 7569,7677.9 7608.4,7677.9 7647.8,7677.9 8378.4,7695.6 8417.7,7695.6 8457.1,7695.6 7569,7717.3 7608.4,7717.3 7647.8,7717.3 8925.3,7788.1 7230.5,7853.1 8665.5,8083.4 8641.9,8160.2 8482.4,8181.8 7307.2,8201.5 7165.5,8219.3 8677.3,8260.6 8853.5,8261 8382,8319.6 7254.1,8326.5
  other v3: 9237.6,6069.9 9002.6,6079.9 8605.6,6084.9 8722.6,6084.9 8498.3,6118.7 9049.4,6181.9 8760,6211.4 8819,6235 9031.6,6240.9 9226.5,6282.2 8931.3,6711.4 9143.9,6711.4 7823.8,6762 7678.9,6795.7 7850.5,6896.4 7679.3,6902.3 8931.3,6911.4 9143.9,6911.4 7541.5,7174 8494.2,7197.6 8555.3,7207 8931.3,7211.4 9143.9,7211.4 7479.1,7246.8 7815.1,7250.7 6985.7,7345 7118.9,7353.7 7290.7,7355 8931.3,7411.4 9143.9,7411.4 9179.1,7627.3 9179.1,7658.9
  other v4: 7165.5,8136.6 8245.2,8181.1 8079.6,8319.7
GPIO0: R54.2 U11.9 U13.104 | length 2407.9
  Top Layer w5.9: U11.9@8234.8,6308 8279.7,6308 8355.4,6383.7 8436.2,6383.7 8541.5,6488.9 v1(8541.5,6500.7) ; U13.104@8614.6,7828.4 8654.9,7868.7 v1@8659.9,7868.7
  Bottom Layer w5.9: 8164.3,6784.2 8165.7,6782.9 ; v1(8541.5,6500.7) 8524.8,6517.4 8431.1,6517.4 8165.7,6782.9 ; v1(8659.6,7870.8) 8541.5,7752.7 8359.8,7752.7 8094.6,7487.6 8094.6,7304 8165.7,7233 8165.7,6782.9
GPIO1: R52.2 U11.11 U13.1 | length 2310.9
  Top Layer w5.9: U11.11@8234.8,6408 8350.7,6408 8361.4,6397.3 8426.3,6397.3 8506.1,6477.1 v1(8506.1,6494.8) ; U13.1@8590,7853.1 8600.5,7853.1 v1(8630.1,7882.6)
  Bottom Layer w5.9: v1(8506.1,6494.8) 8431.4,6494.8 8149.9,6776.3 8149.9,7226.5 8078.9,7297.5 8078.9,7494.1 8353.2,7768.5 8505.4,7768.5 8619.6,7882.6 v1(8630.1,7882.6)
GPIO1_MS: U6.40
GPIO2: H1.6 U13.2 | length 2586.5
  Top Layer w5.9: U13.2@8576.2,7853.1 8576.2,7881.9 8604.4,7910.1 v1(8615.3,7910.1)
  Bottom Layer w5.9: v1(8615.3,7910.1) 8615.3,7900.6 8498.9,7784.2 8346.7,7784.2 8063.1,7500.6 8063.1,7291 8134.2,7219.9 8134.2,6755.3 8413.8,6475.6 8901.8,6475.6 H1.6@8987.6,6561.4
GPIO3: H1.4 U13.3 | length 2626.9
  Top Layer w5: U13.3@8562.4,7853.1 8562.4,7897.2 v1(8596.2,7931)
  Bottom Layer w5.9: v1(8596.2,7931) 8596.2,7903.8 8492.4,7800 8340.2,7800 8047.4,7507.2 8047.4,7284.4 8118.4,7213.4 8118.4,6748.8 8407.3,6459.9 H1.4@8986.1,6459.9 ; H1.4@8973.8,6447.6 H1.4@8986.1,6459.9 ; H1.4@8987.6,6461.4 H1.4@8986.1,6459.9
GPIO4: U11.1 U13.4 | length 1818
  Top Layer w5.9: U11.1@7997.8,6658 v1@8110.4,6658 ; U13.4@8548.6,7853.1 8548.6,7908.6 v1(8571,7931)
  Bottom Layer w5.9: v1@8110.4,6658 8102.7,6665.7 8102.7,7206.9 8031.6,7277.9 8031.6,7513.7 8333.7,7815.7 8485.9,7815.7 8571,7900.9 v1(8571,7931)
  other v1: 8110.4,6660.2
GPIO5: U11.3 U13.5 | length 1901.9
  Top Layer w5.9: U11.3@7997.8,6558 8086.8,6558 v1@8110.4,6581.7 ; U13.5@8534.9,7853.1 8534.9,7920 v1(8545.8,7931)
  Bottom Layer w5.9: v1@8110.4,6581.7 8110.4,6589.3 8086.9,6612.8 8086.9,7200.4 8015.9,7271.4 8015.9,7520.2 8327.2,7831.5 8479.3,7831.5 8545.8,7897.9 v1(8545.8,7931)
  other v1: 8110.4,6583.4
GPIO13: R22.2 U7.3 U13.14 | length 1819.9
  Top Layer w5.9: U7.3@7922.1,6708.4 7944.8,6731.1 v3(7956.8,6731.1) ; v1(8373.2,8001.7) 8410.9,7964 U13.14@8410.9,7853.1
  Top Layer w7.9: R22.2@7986.5,7675.9 8057.2,7675.9 v1(8075,7658.2)
  Bottom Layer w5.9: v3(7956.8,6731.1) 7980.5,6731.1 8039.7,6790.3 8039.7,7180.8 7968.7,7251.8 7968.7,7539.8 8299.4,7870.5 8299.4,7888.5 8346.6,7935.8 8346.6,7975.1 v1(8373.2,8001.7)
GPIO14: U13.15
GPIO16: R35.1 U5.5 U13.17 | length 782.4
  Top Layer w5.9: R35.1@8004.2,8042.1 8033.6,8042.1 8069,8077.5 8069,8130.7 v3(8039.5,8160.2) 8017.9,8160.2 U5.5@8010,8168.1 ; v1@8328.9,8077.5 8350.7,8055.7 8350.7,7990.7 8358.4,7983 8358.4,7960.3 8382,7936.7 8382,7900.4 8369.5,7887.8 U13.17@8369.5,7853.1
  VCC w5.9: v3(8039.5,8160.2) 8051.3,8160.2 8110.4,8101.1 8305.3,8101.1 v1@8328.9,8077.5
  other v1: 8327.4,8077.8
GPIO17: R48.1 U13.18 | length 1583
  Top Layer w5.9: U13.18@8355.7,7853.1 8355.7,7896.8 8364.3,7905.4 v1(8364.3,7929.9)
  Top Layer w7.9: R48.1@7075.8,8331.5 7075.8,8291.3 v4(7082.8,8284.2)
  VCC w5.9: v4(7082.8,8284.2) 7100.5,8266.5 7614.3,8266.5 7643.9,8237 7933.2,8237 8122.2,8048 8287.6,8048 8349.2,7986.3 8349.2,7945 v1(8364.3,7929.9)
GPIO18: R21.2 U10.1 U13.19 | length 1217.4
  Top Layer w6.1: v1(8323,7977.1) 8346.6,7953.5 8346.6,7906.3 8342,7901.6 U13.19@8342,7853.1
  Top Layer w10: R21.2@7460.9,8343.3 7484.4,8343.3 7525.7,8301.9 7525.7,8244.6 7537.5,8232.8 U10.1@7537.5,8219.3
  VCC w5.9: v2(7525.7,8242.9) 7531.6,8248.8 7608.4,8248.8 7637.9,8219.3 7927.3,8219.3 8116.3,8030.3 8269.8,8030.3 v1(8323,7977.1)
GPIO36: R26.1 U13.68 | length 386.8
  Top Layer w5: U13.68@8452.2,7459.4 8452.2,7427.9 v1(8455.5,7424.6)
  Top Layer w5.9: v1(8718.7,7427.9) 8747.9,7427.9 R26.1@8777.4,7398.4
  Bottom Layer w5: v1(8455.5,7424.6) 8471.4,7408.7 8707.6,7408.7 8716.7,7417.8 v1@8716.7,7426
GPIO49: U13.92
GPIO50: U13.93 U17.4 | length 2120
  Top Layer w5.9: v1(8594.6,6518.5) 8634,6518.5 8763.9,6388.5 U17.4@8779.6,6388.5 ; U13.93@8614.6,7676.9 8637,7676.9 v1@8641.9,7672
  Bottom Layer w5.9: v1(8594.6,6518.5) 8555.8,6557.3 8447.7,6557.3 8197.2,6807.8 8197.2,7246 8126.1,7317.1 8126.1,7474.5 8372.8,7721.2 8573,7721.2 8622.2,7672 v1@8641.9,7672
  other v1: 8641.9,7670
GPIO51: U13.94 U17.5 | length 2366.2
  Top Layer w5: U13.94@8614.6,7690.7 8744,7690.7 v1(8746.3,7688.4)
  Top Layer w5.9: v1(8582.8,6494.8) 8634,6494.8 8752.1,6376.7 U17.5@8752.1,6361
  Bottom Layer w5.9: v1(8582.8,6494.8) 8536.1,6541.6 8441.2,6541.6 8181.4,6801.3 8181.4,7239.5 8110.4,7310.5 8110.4,7481.1 8366.3,7737 8580.9,7737 8629.4,7688.4 v1(8746.3,7688.4)
HDMI_0+: D3.1 D3.10 HDMI1.7 U6.29 | length 383.3
  Top Layer w4.7: HDMI1.7@7099,7697.6 7154.8,7697.6 7168.2,7710.9 7276.7,7710.9 7280.2,7707.5 D3.10@7296.9,7707.5 ; D3.1@7329.5,7707.5 7346.2,7707.5 7349.7,7710.9 7442.7,7710.9 7446.2,7707.5 U6.29@7470.6,7707.5
  Top Layer w4.9: D3.10@7295.8,7707.3 D3.1@7330.5,7707.3
HDMI_0-: D3.2 D3.9 HDMI1.9 U6.28 | length 383.6
  Top Layer w4.7: HDMI1.9@7099,7737 7154.8,7737 7168.2,7723.6 7276.7,7723.6 7280.2,7727.1 D3.9@7296.9,7727.1 ; D3.2@7329.5,7727.1 7346.2,7727.1 7349.7,7723.6 7442.7,7723.6 7446.2,7727.1 U6.28@7470.6,7727.1
  Top Layer w4.9: D3.9@7295.8,7727 D3.2@7330.5,7727
HDMI_1+: D2.4 D2.7 HDMI1.4 U6.32 | length 381.4
  Top Layer w4.7: HDMI1.4@7099,7638.6 7154.8,7638.6 7168.2,7651.9 7276.7,7651.9 7280.2,7648.4 D2.7@7296.9,7648.4 D2.4@7329.5,7648.4 7346.2,7648.4 7349.7,7651.9 7442.7,7651.9 7446.2,7648.4 U6.32@7470.6,7648.4
HDMI_1-: D2.5 D2.6 HDMI1.6 U6.31 | length 381.4
  Top Layer w4.7: HDMI1.6@7099,7677.9 7154.8,7677.9 7168.2,7664.6 7276.7,7664.6 7280.2,7668.1 D2.6@7296.9,7668.1 D2.5@7329.5,7668.1 7346.2,7668.1 7349.7,7664.6 7442.7,7664.6 7446.2,7668.1 U6.31@7470.6,7668.1
HDMI_2+: D2.1 D2.10 HDMI1.1 U6.35 | length 381.4
  Top Layer w4.7: HDMI1.1@7099,7579.5 7154.8,7579.5 7168.2,7592.8 7276.7,7592.8 7280.2,7589.3 D2.10@7296.9,7589.3 D2.1@7329.5,7589.3 7346.2,7589.3 7349.7,7592.8 7442.7,7592.8 7446.2,7589.3 U6.35@7470.6,7589.3
HDMI_2-: D2.2 D2.9 HDMI1.3 U6.34 | length 381.5
  Top Layer w4.7: HDMI1.3@7099,7618.9 7154.8,7618.9 7168.2,7605.5 7276.7,7605.5 7280.2,7609 D2.9@7296.9,7609 D2.2@7329.5,7609 7346.2,7609 7349.7,7605.5 7442.7,7605.5 7446.2,7609 U6.34@7470.6,7609
HDMI_5V: C20.2 D4.2 HDMI1.18 R38.1 R39.1 R40.1 | length 657.1
  Top Layer w11.8: HDMI1.18@7099,7914.2 7167.5,7914.2 7174.5,7921.1 C20.2@7272.6,7921.1 7286.7,7921.1 7313.1,7947.6 7313.1,8030.3 7283.6,8059.8 7180.4,8059.8 R39.1@7122.3,8118 R38.1@7122.3,8177.5 ; R38.1@7122.5,8177.7 R38.1@7122.3,8177.5 ; R40.1@7122.5,8237 7122.3,8236.7 R38.1@7122.3,8177.5
HDMI_C+: D3.4 D3.7 HDMI1.10 U6.26 | length 381.4
  Top Layer w4.7: HDMI1.10@7099,7756.7 7154.8,7756.7 7168.2,7770 7276.7,7770 7280.2,7766.5 D3.7@7296.9,7766.5 D3.4@7329.5,7766.5 7346.2,7766.5 7349.7,7770 7442.7,7770 7446.2,7766.5 U6.26@7470.6,7766.5
HDMI_C-: D3.5 D3.6 HDMI1.12 U6.25 | length 381.4
  Top Layer w4.7: HDMI1.12@7099,7796 7154.8,7796 7168.2,7782.7 7276.7,7782.7 7280.2,7786.2 D3.6@7296.9,7786.2 D3.5@7329.5,7786.2 7346.2,7786.2 7349.7,7782.7 7442.7,7782.7 7446.2,7786.2 U6.25@7470.6,7786.2
HDMIDET: R40.2 U6.18 | length 922.3
  Top Layer w5: U6.18@7618.3,7815.7 7618.3,7951.5 v1(7626.1,7959.4)
  Top Layer w7.9: v2(7041.5,8284.2) 7041.5,8258.6 R40.2@7063.2,8237
  Bottom Layer w10: v2(7041.5,8284.2) 7153.7,8172 7401.7,8172 7614.3,7959.4 v1(7626.1,7959.4)
HDMIHPD: HDMI1.19 U6.17 | length 694.5
  Top Layer w5: v1(7637.6,7933.7) 7637.9,7933.4 U6.17@7637.9,7815.7
  Top Layer w10: HDMI1.19@7099,7933.8 7099,7948.8 v1(7118.9,7968.7)
  Bottom Layer w5: v1(7118.9,7968.7) 7143.9,7943.7 7512.6,7943.7 7522.6,7933.7 v1(7637.6,7933.7)
HDMISCL: HDMI1.15 R38.2 U6.22 | length 1207.5
  Top Layer w5.9: R38.2@7063.2,8177.7 6947,8061.5 v3(6947,7906.3) 6998.2,7855.1 HDMI1.15@7106.8,7855.1
  Top Layer w7.9: U6.22@7539.5,7815.7 7539.5,7860.6 7547.6,7868.7 v1(7547.6,7888.7)
  Bottom Layer w5: v3(6947,7906.3) 6974.4,7933.7 7502.6,7933.7 v1(7547.6,7888.7)
HDMISDA: HDMI1.16 R39.2 U6.21 | length 1128.1
  Top Layer w5.9: R39.2@7062.9,8118 7034.7,8118 6962,8045.3 6962,7923.4 v3(7010.6,7874.8) HDMI1.16@7106.8,7874.8
  Top Layer w7.9: U6.21@7559.2,7815.7 7559.2,7860.3 v1(7567.6,7868.7)
  Bottom Layer w5: v3(7010.6,7874.8) 6988.3,7897.1 6988.3,7912.2 7000.1,7924 7484.4,7924 7539.7,7868.7 v1(7567.6,7868.7)
HXIN: C17.1 U6.1 X3.1 | length 329.5
  Top Layer w5: U6.1@7746,7569.7 7841.6,7569.7 7867.6,7543.7 7867.6,7485.9 X3.1@7829.9,7448.2
  Top Layer w6.1: C17.1@7752.6,7427.2 7808.8,7427.2 X3.1@7829.9,7448.2
HXOUT: C18.1 U6.2 X3.3 | length 322.9
  Top Layer w5: U6.2@7746.2,7589.3 7842.3,7589.3 X3.3@7916.5,7515.1 7901.2,7515.1 X3.3@7896.5,7519.8 ; X3.3@7896.5,7505.1 X3.3@7896.5,7519.8 ; X3.3@7896.5,7532.7 X3.3@7896.5,7519.8
  Top Layer w6.1: X3.3@7916.5,7515.1 7931.6,7530.2 C18.1@7982.6,7530.2
LED_MS: MS_LED1.1 U6.39 | length 62.9
  Top Layer w7.9: MS_LED1.1@7525.6,7483 7539.5,7496.9 U6.39@7539.5,7540.1
MDC: U13.22 U19.16 | length 1395.8
  Top Layer w5.9: U19.16@7734.4,7024.9 7734.4,7006.6 v1(7738.3,7002.7)
  Top Layer w6.1: U13.22@8300.6,7853.1 8300.6,7953.5 v1@8307.6,7960.5
  Bottom Layer w5.9: v1(7738.3,7002.7) 7714.7,7026.3 7714.7,7320.5 7852.6,7458.4 7852.6,7588.3 8128.7,7864.4 8186.7,7864.4 8246.2,7924 8271.1,7924 v1@8307.6,7960.5
  other v1: 8305.3,7959.4
MDIO: R11.1 U13.23 U19.15 | length 1469.1
  Top Layer w5: U13.23@8286.8,7853.1 8286.8,7982.3 v1(8287.6,7983)
  Top Layer w5.9: U19.15@7714.7,7024.9 v1(7714.7,6999.2) 7714.7,6988.3 R11.1@7730.5,6972.5
  Bottom Layer w5.9: v1(7714.7,6999.2) 7699.7,7014.2 7699.7,7326.7 7837.6,7464.6 7837.6,7594.5 8122.5,7879.4 8178.1,7879.4 8240.8,7942.2 8264.4,7942.2 8287.6,7965.3 v1(8287.6,7983)
MS_SCL: H1.3 R31.1 R36.1 U5.1 U6.13 | length 4083.7
  Top Layer w5.9: R31.1@8849.6,7567.5 8865.1,7551.9 9132,7551.9 v1(9143.9,7563.7)
  Top Layer w6.1: U5.1@8010,8260.6 v3(8010,8299.9)
  Top Layer w10: U6.13@7716.7,7815.7 7716.7,7908.2 7731.5,7923 7731.5,7971.6 v3(7725.6,7977.5) 7755.3,7977.5 R36.1@7766.9,7989.1
  VCC w5.9: v3(8010,8299.9) 8010,8248.8 8122.2,8136.6 9078.9,8136.6 9220.6,7994.8 9220.6,7611 9173.4,7563.7 v1(9143.9,7563.7) 9143.9,7540.1 9220.6,7463.3 9220.6,6565.7 9155.8,6500.9 9127,6500.9 H1.3@9087.6,6461.4
  Bottom Layer w6.1: v3(7725.6,7977.5) 7725.6,8031.7 7930.9,8237 7980.5,8237 8010,8266.5 v3(8010,8299.9)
